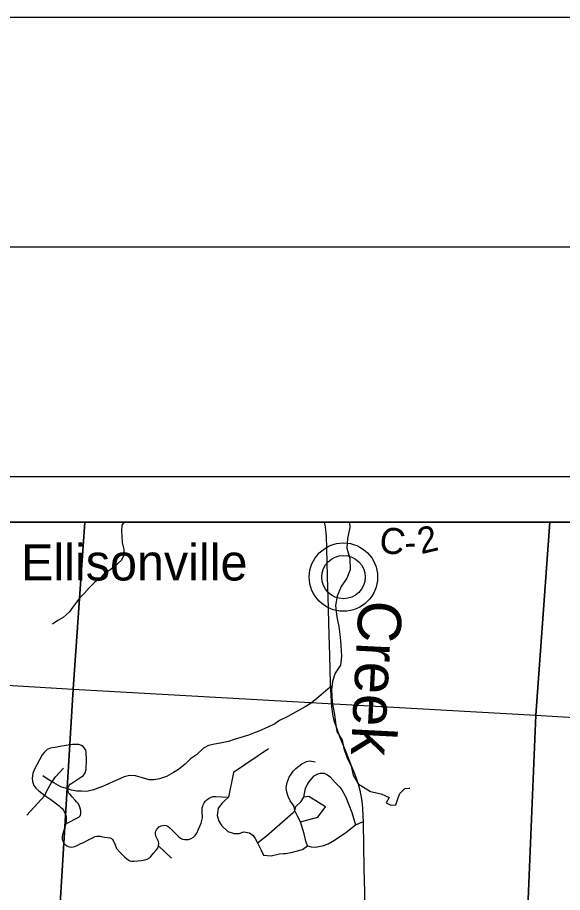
# Model space of a CAD drawing. Extents: x 0 to 34, y 0 to 22.
# Drawn here: x 3.758 to 4.945, y 20.093 to 22 of the extents above; entities that cross this region are included whole.
import ezdxf

# ---------------------------------------------------------------- set-up
doc = ezdxf.new("R2010")
doc.units = 0
for name, color, linetype in [('GM_X_Corporation', 7, 'Continuous'), ('GM_X_County_Road_Text', 7, 'Continuous'), ('GM_X_Minor_River', 7, 'Continuous'), ('GM_X_Minor_River_Text', 7, 'Continuous'), ('GM_X_State_Route', 7, 'Continuous'), ('GM_X_Township_Road', 7, 'Continuous'), ('GM_X_Unincorporated', 7, 'Continuous'), ('GM_X_Unincorporated_Location', 7, 'Continuous'), ('GM_X_Unincorporated_Text', 7, 'Continuous'), ('SH_Border', 7, 'Continuous'), ('SH_Data', 7, 'Continuous')]:
    doc.layers.add(name, color=color, linetype=linetype)

msp = doc.modelspace()

# ---------------------------------------------------------------- linework, layer by layer
at = {"layer": 'GM_X_Corporation'}
for points in [[(3.3441, 14.1), (8.9, 14.1), (8.9, 20.9), (2.1, 20.9), (2.1, 16.1353), (2.1457, 16.065), (2.3447, 15.6926), (2.4297, 15.5215), (2.465, 15.4504), (2.4884, 15.4033), (2.5769, 15.2135), (2.7849, 14.8403), (2.8931, 14.6544), (3.0297, 14.4867), (3.1386, 14.3654), (3.228, 14.2415)], [(6.9348, 20.9), (2.1, 20.9), (2.1, 19.6396), (2.105, 19.6393), (2.5886, 19.6074), (3.0215, 19.5789), (3.8201, 19.5262), (3.8692, 19.5228), (4.8375, 19.4557), (5.0201, 19.4401), (5.6539, 19.3859), (5.9419, 19.3649), (6.5423, 19.3229), (6.824, 19.3005), (6.835, 19.4037), (6.8961, 20.3303), (6.9032, 20.4198)], [(3.9048, 20.9), (2.8947, 20.9), (2.8805, 20.5967), (3.8795, 20.5363)], [(4.9179, 20.9), (3.9048, 20.9), (3.8795, 20.5363), (4.8871, 20.4794)], [(5.9334, 20.9), (4.9179, 20.9), (4.8871, 20.4794), (5.901, 20.4176)], [(3.8795, 20.5363), (3.8179, 19.5177), (2.8266, 19.5815), (2.8805, 20.5967)], [(4.8871, 20.4794), (4.8445, 19.4512), (3.8179, 19.5177), (3.8795, 20.5363)], [(4.8871, 20.4794), (5.901, 20.4176), (5.8355, 19.3781), (4.8445, 19.4512)]]:
    msp.add_lwpolyline(points, close=True, dxfattribs=at)
at = {"layer": 'GM_X_Minor_River'}
for points in [[(3.9908, 20.9), (3.9858, 20.8937), (3.985, 20.8808), (3.9854, 20.8687), (3.9865, 20.8562), (3.9903, 20.8406), (3.9911, 20.8296), (3.985, 20.8175), (3.9699, 20.8035), (3.9601, 20.7966), (3.9472, 20.7879), (3.9381, 20.7777), (3.9268, 20.7697), (3.9147, 20.7568), (3.9034, 20.745), (3.8943, 20.7355), (3.8867, 20.7261), (3.878, 20.7139), (3.8712, 20.7037), (3.8576, 20.6923), (3.8463, 20.6858), (3.8349, 20.6779)], [(4.4816, 20.9), (4.4822, 20.8884), (4.4772, 20.8648), (4.476, 20.8432), (4.482, 20.8211), (4.4827, 20.796), (4.4755, 20.7782), (4.4633, 20.7599), (4.4546, 20.7386), (4.4511, 20.7185), (4.4537, 20.693), (4.4586, 20.6725), (4.4615, 20.6493), (4.4626, 20.6314), (4.4645, 20.6078), (4.4618, 20.5884), (4.4504, 20.5709), (4.4443, 20.5531), (4.4424, 20.5348), (4.4438, 20.5082), (4.449, 20.4812), (4.4509, 20.4626), (4.4543, 20.4439), (4.4656, 20.4253), (4.4693, 20.407), (4.4757, 20.388), (4.4851, 20.3682), (4.4896, 20.3488), (4.5002, 20.3302)], [(4.4424, 20.5348), (4.4423, 20.5428), (4.4302, 20.5329), (4.4147, 20.5196), (4.3981, 20.5056), (4.3849, 20.498), (4.372, 20.4908), (4.3588, 20.4832), (4.3475, 20.4764), (4.3289, 20.4676), (4.3187, 20.4604), (4.3036, 20.4532), (4.2843, 20.4449), (4.2722, 20.4403), (4.2616, 20.4357), (4.245, 20.4308), (4.2306, 20.4266), (4.2178, 20.4225), (4.2, 20.4186), (4.1875, 20.4167), (4.1747, 20.4137), (4.1634, 20.408), (4.1482, 20.3928), (4.1354, 20.3841), (4.1233, 20.3731), (4.1093, 20.3613), (4.0983, 20.3549), (4.0828, 20.3462), (4.0677, 20.3405), (4.0552, 20.3386), (4.045, 20.3389), (4.031, 20.3427), (4.0155, 20.3476), (4.0027, 20.348), (3.9906, 20.345), (3.9762, 20.3389), (3.9596, 20.3313), (3.946, 20.3248), (3.9358, 20.321), (3.9237, 20.3169), (3.9097, 20.3134), (3.898, 20.3138), (3.8878, 20.3138), (3.8764, 20.3161), (3.8655, 20.3195), (3.853, 20.3237), (3.8379, 20.332), (3.825, 20.3396), (3.8137, 20.3475)], [(4.5002, 20.3302), (4.527, 20.3131), (4.5505, 20.3081), (4.5676, 20.3004)], [(4.5676, 20.3004), (4.5614, 20.2887), (4.5716, 20.2834), (4.5822, 20.2841), (4.5879, 20.2993), (4.591, 20.3087), (4.602, 20.3201), (4.613, 20.3204), (4.6126, 20.3208)]]:
    msp.add_lwpolyline(points, dxfattribs=at)
at = {"layer": 'GM_X_State_Route'}
for points in [[(4.4349, 20.7402), (4.4345, 20.7551), (4.4339, 20.7845), (4.4328, 20.8108), (4.4322, 20.8435), (4.4312, 20.8696), (4.4293, 20.8903), (4.4274, 20.9)], [(4.5153, 20.0743), (4.5146, 20.0938), (4.5138, 20.145), (4.5131, 20.1979), (4.5128, 20.2081), (4.5123, 20.2323), (4.5119, 20.2476), (4.5116, 20.2589), (4.5107, 20.2767), (4.5093, 20.2922), (4.5073, 20.3044), (4.505, 20.3152), (4.5012, 20.3292), (4.4975, 20.3396), (4.4932, 20.3515), (4.487, 20.3669), (4.4808, 20.3825), (4.474, 20.399), (4.4607, 20.4321), (4.4522, 20.4556), (4.4491, 20.4652), (4.4462, 20.4772), (4.4444, 20.4876), (4.4431, 20.4975), (4.442, 20.5085), (4.4415, 20.5235), (4.44, 20.5478), (4.4384, 20.6094), (4.4376, 20.6544), (4.4357, 20.7093), (4.4349, 20.7402)]]:
    msp.add_lwpolyline(points, dxfattribs=at)
at = {"layer": 'GM_X_Township_Road'}
for p, q in [((3.7789, 20.2616), (3.8178, 20.3042)), ((4.0659, 20.195), (4.0936, 20.1682))]:
    msp.add_line(p, q, dxfattribs=at)
for points in [[(3.8636, 20.2431), (3.8919, 20.2574), (3.8948, 20.2603), (3.8964, 20.2647), (3.8964, 20.2702), (3.8957, 20.2742), (3.8943, 20.2788), (3.8925, 20.2832), (3.8904, 20.2867), (3.8872, 20.2904), (3.8837, 20.2946), (3.8774, 20.3016), (3.8736, 20.3057), (3.8713, 20.3084), (3.8697, 20.3111), (3.8687, 20.3143), (3.8685, 20.317), (3.8685, 20.3203), (3.8696, 20.3235), (3.8709, 20.3262), (3.8733, 20.3294), (3.8766, 20.3313), (3.8897, 20.3399), (3.8967, 20.3446), (3.902, 20.3483), (3.9058, 20.3537), (3.9083, 20.3612), (3.909, 20.3826), (3.9081, 20.398), (3.9074, 20.403), (3.9047, 20.4078), (3.9015, 20.4112), (3.8981, 20.4135), (3.8922, 20.4155), (3.8879, 20.4157), (3.8833, 20.4157), (3.8783, 20.4157), (3.8504, 20.411), (3.8404, 20.4094), (3.8341, 20.4085), (3.8302, 20.4073), (3.8268, 20.4062), (3.8234, 20.4044), (3.8207, 20.4026), (3.817, 20.3989), (3.8125, 20.3932), (3.7948, 20.3601), (3.7916, 20.3524), (3.7902, 20.3426), (3.7911, 20.3351), (3.7941, 20.3265), (3.7982, 20.3208), (3.8047, 20.3143), (3.8178, 20.3042), (3.8311, 20.2961), (3.8371, 20.2911), (3.8432, 20.2866), (3.8489, 20.2821), (3.8524, 20.2791), (3.8558, 20.2758), (3.8585, 20.2724), (3.8611, 20.2677), (3.863, 20.2635), (3.8641, 20.2589), (3.8646, 20.2539), (3.8641, 20.2491), (3.8636, 20.2431), (3.8566, 20.2189), (3.8561, 20.2159), (3.8557, 20.213), (3.8561, 20.2096), (3.8573, 20.2049), (3.8601, 20.2), (3.8636, 20.1964), (3.8659, 20.195), (3.8689, 20.1935), (3.8718, 20.1927), (3.8755, 20.192), (3.8795, 20.1923), (3.8832, 20.193), (3.8895, 20.1959), (3.8952, 20.1989), (3.9033, 20.2026), (3.9142, 20.2084), (3.9219, 20.2125), (3.9277, 20.2149), (3.9312, 20.216), (3.9348, 20.2161), (3.9384, 20.2158), (3.9405, 20.2154), (3.9481, 20.214), (3.9542, 20.2133), (3.96, 20.2125), (3.9633, 20.2105), (3.9656, 20.2084), (3.9677, 20.2047), (3.9709, 20.1967), (3.9738, 20.1891), (3.981, 20.1809), (3.9923, 20.1703), (3.9956, 20.1675), (3.9989, 20.1647), (4.0033, 20.1623), (4.007, 20.1614), (4.0126, 20.1611), (4.0207, 20.1621), (4.0287, 20.163), (4.0361, 20.1642), (4.041, 20.166), (4.0457, 20.1688), (4.0489, 20.1718), (4.0549, 20.1786), (4.0606, 20.1856), (4.064, 20.1898), (4.0659, 20.195), (4.0664, 20.1999), (4.0657, 20.204), (4.0635, 20.2086), (4.0618, 20.2114), (4.0603, 20.2143), (4.0594, 20.217), (4.0589, 20.22), (4.0592, 20.2238), (4.0598, 20.2267), (4.0611, 20.2294), (4.0628, 20.232), (4.0645, 20.2341), (4.0664, 20.2359), (4.0683, 20.2371), (4.0713, 20.2383), (4.0747, 20.2393), (4.0781, 20.2395), (4.0819, 20.2388), (4.0863, 20.2371), (4.0903, 20.2339), (4.0935, 20.231), (4.1005, 20.2238), (4.1097, 20.2145), (4.1137, 20.2113), (4.1181, 20.2094), (4.1227, 20.2085), (4.1307, 20.2083), (4.1368, 20.2105), (4.1419, 20.2134), (4.1453, 20.2171), (4.1491, 20.2227), (4.1525, 20.2314), (4.1582, 20.2443), (4.1615, 20.2555), (4.1611, 20.2588), (4.1608, 20.2665), (4.1609, 20.2725), (4.161, 20.2774), (4.1618, 20.2811), (4.1629, 20.2844), (4.1652, 20.2887), (4.1679, 20.2924), (4.1706, 20.2954), (4.1744, 20.2983), (4.1802, 20.3011), (4.1844, 20.3022), (4.1906, 20.3025), (4.2035, 20.3019), (4.2177, 20.301)], [(4.3055, 20.4061), (4.229, 20.3545), (4.2177, 20.301), (4.2116, 20.2949), (4.2033, 20.2873), (4.1952, 20.2771), (4.193, 20.2611), (4.1971, 20.2489), (4.2032, 20.2387), (4.2164, 20.2257), (4.2305, 20.2219), (4.2416, 20.2219), (4.2515, 20.225), (4.264, 20.2231), (4.2718, 20.217), (4.2764, 20.2105), (4.2815, 20.201), (4.2881, 20.1865), (4.2939, 20.1741), (4.3111, 20.1729), (4.329, 20.1771), (4.3381, 20.178)], [(4.3581, 20.2847), (4.3526, 20.2927), (4.3479, 20.3023), (4.3449, 20.3116), (4.3439, 20.322), (4.3455, 20.3331), (4.3502, 20.3445), (4.3592, 20.3574), (4.3647, 20.3636), (4.3774, 20.3733), (4.388, 20.3788), (4.3953, 20.3802), (4.4066, 20.3781)], [(3.8178, 20.3042), (3.8219, 20.3134), (3.8315, 20.3317), (3.8413, 20.3451), (3.8588, 20.3637)], [(4.2815, 20.201), (4.3009, 20.2166), (4.3586, 20.2672), (4.3627, 20.2711), (4.3647, 20.2803), (4.3753, 20.2904), (4.3822, 20.301), (4.3836, 20.3089), (4.3857, 20.3195), (4.3907, 20.3307), (4.396, 20.3369), (4.4043, 20.3471), (4.4114, 20.3512), (4.4179, 20.3531), (4.4264, 20.3528), (4.4335, 20.3493), (4.4395, 20.3451), (4.4506, 20.3329), (4.4604, 20.3224), (4.465, 20.317), (4.4737, 20.3006), (4.487, 20.2672), (4.4943, 20.2409)], [(4.3745, 20.2472), (4.4127, 20.2573), (4.429, 20.2795), (4.3929, 20.3021), (4.3822, 20.301)], [(4.3901, 20.1946), (4.3866, 20.2051), (4.383, 20.2213), (4.3745, 20.2472), (4.3683, 20.2591), (4.3627, 20.2711), (4.3609, 20.2807), (4.3581, 20.2847)], [(4.3381, 20.178), (4.3421, 20.1784), (4.3547, 20.1803), (4.3795, 20.1866), (4.3901, 20.1946), (4.3981, 20.1923), (4.4072, 20.1919), (4.4255, 20.1953), (4.435, 20.1995), (4.449, 20.2075), (4.4737, 20.2242), (4.4943, 20.2409), (4.5119, 20.2476)]]:
    msp.add_lwpolyline(points, dxfattribs=at)
at = {"layer": 'GM_X_Unincorporated'}
for radius in [0.0744, 0.0472]:
    msp.add_circle((4.4684, 20.7805), radius, dxfattribs=at)
at = {"layer": 'GM_X_Unincorporated_Location'}
msp.add_line((4.4684, 20.7805), (4.4684, 20.7805), dxfattribs=at)
at = {"layer": 'SH_Border'}
msp.add_lwpolyline([(1.5, 21.5), (33.5, 21.5), (33.5, 0.5), (1.5, 0.5)], close=True, dxfattribs=at)
at = {"layer": 'SH_Data'}
for p, q in [((2, 21), (9, 21)), ((2.1, 20.9), (8.9, 20.9))]:
    msp.add_line(p, q, dxfattribs=at)
msp.add_lwpolyline([(0, 0), (34, 0), (34, 22), (0, 22)], close=True, dxfattribs=at)

# ---------------------------------------------------------------- texts
at = {"layer": 'GM_X_County_Road_Text'}
for s, rotation, p in [('C', 350.4761, (4.5434, 20.8359)), ('2', 13.542, (4.6375, 20.8301)), ('-', 2.4668, (4.6023, 20.8274))]:
    msp.add_text(s, height=0.0568, rotation=rotation, dxfattribs=at).set_placement(p)
at = {"layer": 'GM_X_Minor_River_Text'}
msp.add_text('Creek', height=0.09468, rotation=267.0459, dxfattribs=at).set_placement((4.502, 20.7313))
at = {"layer": 'GM_X_Unincorporated_Text'}
msp.add_text('Ellisonville', height=0.078977, rotation=0, dxfattribs=at).set_placement((3.7663, 20.7731))

doc.saveas('drawing.dxf')
